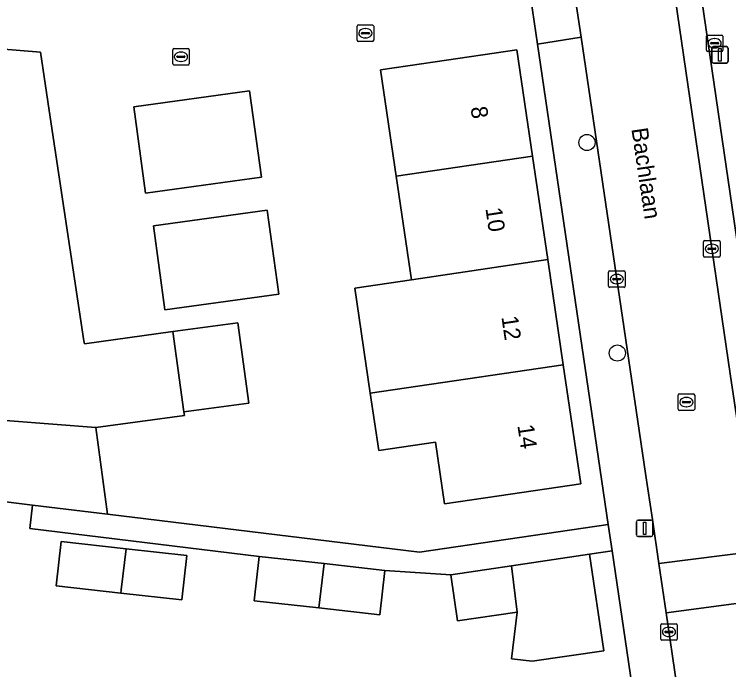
# Model space of a CAD drawing. Extents: x 159053 to 160042, y 380449 to 381423.
# Drawn here: x 159448.97 to 159492.17, y 381206.15 to 381245.81 of the extents above; entities that cross this region are included whole.
import ezdxf

# ---------------------------------------------------------------- set-up
doc = ezdxf.new("R2010")
doc.units = 0
for name, color, linetype in [('IMGEO_Boom', 7, 'Continuous'), ('IMGEO_Brandkraan', 7, 'Continuous'), ('IMGEO_Erf', 7, 'Continuous'), ('IMGEO_Kolk', 7, 'Continuous'), ('IMGEO_Lichtmast', 7, 'Continuous'), ('IMGEO_Openbare_ruimte_label', 7, 'Continuous'), ('IMGEO_Pand', 7, 'Continuous'), ('IMGEO_Pand_nummerreeks', 7, 'Continuous'), ('IMGEO_Parkeervlak_open', 7, 'Continuous'), ('IMGEO_Rijbaan_lokaal_open', 7, 'Continuous'), ('IMGEO_Rioolput', 7, 'Continuous'), ('IMGEO_Voetpad_open', 7, 'Continuous')]:
    doc.layers.add(name, color=color, linetype=linetype)

msp = doc.modelspace()

# ---------------------------------------------------------------- linework, layer by layer
at = {"layer": 'IMGEO_Boom'}
for centre in [(159483.6, 381238.048), (159485.436, 381225.309)]:
    msp.add_circle(centre, 0.489, dxfattribs=at)
at = {"layer": 'IMGEO_Brandkraan'}
for p, q in [((159490.822, 381243.628), (159490.822, 381244.48)), ((159490.897, 381244.554), (159491.749, 381244.554)), ((159491.823, 381244.48), (159491.823, 381243.628)), ((159491.081, 381244.048), (159491.081, 381244.06)), ((159491.519, 381244.011), (159491.121, 381244.011)), ((159491.124, 381244.097), (159491.522, 381244.097)), ((159491.31, 381244.334), (159491.335, 381244.334)), ((159491.565, 381244.06), (159491.565, 381244.048)), ((159491.749, 381243.554), (159490.897, 381243.554)), ((159491.333, 381243.774), (159491.308, 381243.774))]:
    msp.add_line(p, q, dxfattribs=at)
for points in [[(159490.822, 381243.628), (159490.822, 381244.48)], [(159490.897, 381244.554), (159491.749, 381244.554)], [(159491.823, 381244.48), (159491.823, 381243.628)], [(159491.749, 381243.554), (159490.897, 381243.554)]]:
    msp.add_lwpolyline(points, dxfattribs=at)
for centre, radius, start, end in [((159490.899, 381244.478), 0.0765, 91.552, 178.448), ((159490.899, 381244.478), 0.0765, 91.552, 178.448), ((159491.747, 381244.478), 0.0765, 1.552, 88.448), ((159491.747, 381244.478), 0.0765, 1.552, 88.448), ((159491.121, 381244.057), 0.0403, 85.8775, 175.7526), ((159491.118, 381244.047), 0.0366, 178.938, 274.7102), ((159491.522, 381244.054), 0.043, 264.8664, 352.4533), ((159491.526, 381244.059), 0.0386, 1.7309, 96.639), ((159490.899, 381243.63), 0.0765, 181.552, 268.448), ((159490.899, 381243.63), 0.0765, 181.552, 268.448), ((159491.747, 381243.63), 0.0765, 271.552, 358.448), ((159491.747, 381243.63), 0.0765, 271.552, 358.448)]:
    msp.add_arc(centre, radius, start, end, dxfattribs=at)
for centre, major_axis, ratio, start_param, end_param in [((159491.309, 381244.054), (-0.387, 0.002), 0.722429, 4.712389, 7.853982), ((159491.334, 381244.054), (-0.39, 0.002), 0.717154, 1.570796, 4.712389)]:
    msp.add_ellipse(centre, major_axis=major_axis, ratio=ratio, start_param=start_param, end_param=end_param, dxfattribs=at)
at = {"layer": 'IMGEO_Erf'}
for points in [[(159442.411, 381244.175), (159450.548, 381243.517), (159451.14, 381239.591), (159453.182, 381226.043), (159453.205, 381225.876), (159458.563, 381226.605), (159462.483, 381227.139), (159463.144, 381222.283), (159459.224, 381221.75), (159459.254, 381221.532), (159453.896, 381220.798), (159454.61, 381215.559), (159473.478, 381213.258), (159484.891, 381214.936), (159480.617, 381244.005), (159479.909, 381248.818)], [(159488.937, 381187.416), (159485.126, 381213.338), (159483.757, 381213.137), (159484.616, 381207.298), (159480.282, 381206.66), (159479.028, 381206.806), (159479.388, 381209.64), (159475.769, 381209.107), (159475.358, 381211.9), (159471.378, 381212.157), (159471.078, 381209.475), (159467.392, 381209.888), (159463.482, 381210.326), (159463.782, 381213.007), (159449.9, 381214.7), (159450.073, 381216.112), (159443.885, 381216.867)]]:
    msp.add_lwpolyline(points, dxfattribs=at)
for points in [[(159479.36, 381243.661), (159480.307, 381237.228), (159481.23, 381230.965), (159482.166, 381224.604), (159483.228, 381217.393), (159478.282, 381216.665), (159474.983, 381216.179), (159474.432, 381219.923), (159471.004, 381219.421), (159470.494, 381222.883), (159469.558, 381229.242), (159472.985, 381229.748), (159472.063, 381236.011), (159471.115, 381242.447), (159474.414, 381242.933)], [(159463.199, 381241.178), (159463.92, 381235.956), (159456.91, 381234.989), (159456.189, 381240.211)], [(159464.269, 381233.949), (159464.961, 381228.868), (159458.069, 381227.93), (159457.377, 381233.011)], [(159455.415, 381210.79), (159451.506, 381211.228), (159451.806, 381213.909), (159455.734, 381213.469), (159459.402, 381213.059), (159459.102, 381210.377)]]:
    msp.add_lwpolyline(points, close=True, dxfattribs=at)
at = {"layer": 'IMGEO_Kolk'}
for p, q in [((159469.701, 381244.235), (159469.701, 381245.087)), ((159469.776, 381245.161), (159470.628, 381245.161)), ((159470.189, 381244.941), (159470.214, 381244.941)), ((159470.702, 381245.087), (159470.702, 381244.235)), ((159469.96, 381244.655), (159469.96, 381244.667)), ((159470.398, 381244.618), (159470, 381244.618)), ((159470.003, 381244.704), (159470.401, 381244.704)), ((159470.212, 381244.381), (159470.187, 381244.381)), ((159470.444, 381244.667), (159470.444, 381244.655)), ((159470.628, 381244.161), (159469.776, 381244.161)), ((159458.545, 381242.813), (159458.545, 381243.665)), ((159458.62, 381243.739), (159459.472, 381243.739)), ((159459.033, 381243.519), (159459.058, 381243.519)), ((159459.546, 381243.665), (159459.546, 381242.813)), ((159458.804, 381243.233), (159458.804, 381243.245)), ((159459.242, 381243.196), (159458.844, 381243.196)), ((159458.847, 381243.282), (159459.245, 381243.282)), ((159459.288, 381243.245), (159459.288, 381243.233)), ((159459.472, 381242.739), (159458.62, 381242.739)), ((159459.056, 381242.959), (159459.031, 381242.959)), ((159490.655, 381231.192), (159490.655, 381232.044)), ((159490.73, 381232.118), (159491.582, 381232.118)), ((159491.143, 381231.898), (159491.168, 381231.898)), ((159491.656, 381232.044), (159491.656, 381231.192)), ((159490.914, 381231.612), (159490.914, 381231.624)), ((159491.352, 381231.575), (159490.954, 381231.575)), ((159490.957, 381231.661), (159491.355, 381231.661)), ((159491.398, 381231.624), (159491.398, 381231.612)), ((159491.582, 381231.118), (159490.73, 381231.118)), ((159491.166, 381231.338), (159491.141, 381231.338)), ((159484.903, 381229.361), (159484.903, 381230.213)), ((159484.978, 381230.287), (159485.83, 381230.287)), ((159485.904, 381230.213), (159485.904, 381229.361)), ((159485.162, 381229.781), (159485.162, 381229.793)), ((159485.6, 381229.744), (159485.202, 381229.744)), ((159485.205, 381229.83), (159485.603, 381229.83)), ((159485.391, 381230.067), (159485.416, 381230.067)), ((159485.646, 381229.793), (159485.646, 381229.781)), ((159485.83, 381229.287), (159484.978, 381229.287)), ((159485.414, 381229.507), (159485.389, 381229.507)), ((159488.134, 381208.934), (159488.986, 381208.934)), ((159488.059, 381208.008), (159488.059, 381208.86)), ((159488.547, 381208.714), (159488.572, 381208.714)), ((159489.06, 381208.86), (159489.06, 381208.008)), ((159488.318, 381208.428), (159488.318, 381208.44)), ((159488.756, 381208.391), (159488.358, 381208.391)), ((159488.361, 381208.477), (159488.759, 381208.477)), ((159488.57, 381208.154), (159488.545, 381208.154)), ((159488.802, 381208.44), (159488.802, 381208.428)), ((159488.986, 381207.934), (159488.134, 381207.934))]:
    msp.add_line(p, q, dxfattribs=at)
for points in [[(159469.701, 381244.235), (159469.701, 381245.087)], [(159469.776, 381245.161), (159470.628, 381245.161)], [(159470.702, 381245.087), (159470.702, 381244.235)], [(159470.628, 381244.161), (159469.776, 381244.161)], [(159458.545, 381242.813), (159458.545, 381243.665)], [(159458.62, 381243.739), (159459.472, 381243.739)], [(159459.546, 381243.665), (159459.546, 381242.813)], [(159459.472, 381242.739), (159458.62, 381242.739)], [(159490.655, 381231.192), (159490.655, 381232.044)], [(159490.73, 381232.118), (159491.582, 381232.118)], [(159491.656, 381232.044), (159491.656, 381231.192)], [(159491.582, 381231.118), (159490.73, 381231.118)], [(159484.903, 381229.361), (159484.903, 381230.213)], [(159484.978, 381230.287), (159485.83, 381230.287)], [(159485.904, 381230.213), (159485.904, 381229.361)], [(159485.83, 381229.287), (159484.978, 381229.287)], [(159488.134, 381208.934), (159488.986, 381208.934)], [(159488.059, 381208.008), (159488.059, 381208.86)], [(159489.06, 381208.86), (159489.06, 381208.008)], [(159488.986, 381207.934), (159488.134, 381207.934)]]:
    msp.add_lwpolyline(points, dxfattribs=at)
for centre, radius, start, end in [((159469.778, 381245.085), 0.0765, 91.552, 178.448), ((159469.778, 381245.085), 0.0765, 91.552, 178.448), ((159470.626, 381245.085), 0.0765, 1.552, 88.448), ((159470.626, 381245.085), 0.0765, 1.552, 88.448), ((159470, 381244.664), 0.0403, 85.8775, 175.7526), ((159469.997, 381244.654), 0.0366, 178.938, 274.7102), ((159470.401, 381244.661), 0.043, 264.8664, 352.4533), ((159470.405, 381244.666), 0.0386, 1.7309, 96.639), ((159469.778, 381244.237), 0.0765, 181.552, 268.448), ((159469.778, 381244.237), 0.0765, 181.552, 268.448), ((159470.626, 381244.237), 0.0765, 271.552, 358.448), ((159470.626, 381244.237), 0.0765, 271.552, 358.448), ((159458.622, 381243.663), 0.0765, 91.552, 178.448), ((159458.622, 381243.663), 0.0765, 91.552, 178.448), ((159459.47, 381243.663), 0.0765, 1.552, 88.448), ((159459.47, 381243.663), 0.0765, 1.552, 88.448), ((159458.844, 381243.242), 0.0403, 85.8775, 175.7526), ((159458.841, 381243.232), 0.0366, 178.938, 274.7102), ((159459.245, 381243.239), 0.043, 264.8664, 352.4533), ((159459.249, 381243.244), 0.0386, 1.7309, 96.639), ((159458.622, 381242.815), 0.0765, 181.552, 268.448), ((159458.622, 381242.815), 0.0765, 181.552, 268.448), ((159459.47, 381242.815), 0.0765, 271.552, 358.448), ((159459.47, 381242.815), 0.0765, 271.552, 358.448), ((159490.732, 381232.042), 0.0765, 91.552, 178.448), ((159490.732, 381232.042), 0.0765, 91.552, 178.448), ((159491.58, 381232.042), 0.0765, 1.552, 88.448), ((159491.58, 381232.042), 0.0765, 1.552, 88.448), ((159490.954, 381231.621), 0.0403, 85.8775, 175.7526), ((159490.951, 381231.611), 0.0366, 178.938, 274.7102), ((159491.355, 381231.618), 0.043, 264.8664, 352.4533), ((159491.359, 381231.623), 0.0386, 1.7309, 96.639), ((159490.732, 381231.194), 0.0765, 181.552, 268.448), ((159490.732, 381231.194), 0.0765, 181.552, 268.448), ((159491.58, 381231.194), 0.0765, 271.552, 358.448), ((159491.58, 381231.194), 0.0765, 271.552, 358.448), ((159484.98, 381230.211), 0.0765, 91.552, 178.448), ((159484.98, 381230.211), 0.0765, 91.552, 178.448), ((159485.828, 381230.211), 0.0765, 1.552, 88.448), ((159485.828, 381230.211), 0.0765, 1.552, 88.448), ((159485.202, 381229.79), 0.0403, 85.8775, 175.7526), ((159485.199, 381229.78), 0.0366, 178.938, 274.7102), ((159485.603, 381229.787), 0.043, 264.8664, 352.4533), ((159485.607, 381229.792), 0.0386, 1.7309, 96.639), ((159484.98, 381229.363), 0.0765, 181.552, 268.448), ((159484.98, 381229.363), 0.0765, 181.552, 268.448), ((159485.828, 381229.363), 0.0765, 271.552, 358.448), ((159485.828, 381229.363), 0.0765, 271.552, 358.448), ((159488.136, 381208.858), 0.0765, 91.552, 178.448), ((159488.136, 381208.858), 0.0765, 91.552, 178.448), ((159488.984, 381208.858), 0.0765, 1.552, 88.448), ((159488.984, 381208.858), 0.0765, 1.552, 88.448), ((159488.358, 381208.437), 0.0403, 85.8775, 175.7526), ((159488.355, 381208.427), 0.0366, 178.938, 274.7102), ((159488.759, 381208.434), 0.043, 264.8664, 352.4533), ((159488.763, 381208.439), 0.0386, 1.7309, 96.639), ((159488.136, 381208.01), 0.0765, 181.552, 268.448), ((159488.136, 381208.01), 0.0765, 181.552, 268.448), ((159488.984, 381208.01), 0.0765, 271.552, 358.448), ((159488.984, 381208.01), 0.0765, 271.552, 358.448)]:
    msp.add_arc(centre, radius, start, end, dxfattribs=at)
for centre, major_axis, ratio, start_param, end_param in [((159470.188, 381244.661), (-0.387, 0.002), 0.722429, 4.712389, 7.853982), ((159470.213, 381244.661), (-0.39, 0.002), 0.717154, 1.570796, 4.712389), ((159459.032, 381243.239), (-0.387, 0.002), 0.722429, 4.712389, 7.853982), ((159459.057, 381243.239), (-0.39, 0.002), 0.717154, 1.570796, 4.712389), ((159491.142, 381231.618), (-0.387, 0.002), 0.722429, 4.712389, 7.853982), ((159491.167, 381231.618), (-0.39, 0.002), 0.717154, 1.570796, 4.712389), ((159485.39, 381229.787), (-0.387, 0.002), 0.722429, 4.712389, 7.853982), ((159485.415, 381229.787), (-0.39, 0.002), 0.717154, 1.570796, 4.712389), ((159488.546, 381208.434), (-0.387, 0.002), 0.722429, 4.712389, 7.853982), ((159488.571, 381208.434), (-0.39, 0.002), 0.717154, 1.570796, 4.712389)]:
    msp.add_ellipse(centre, major_axis=major_axis, ratio=ratio, start_param=start_param, end_param=end_param, dxfattribs=at)
at = {"layer": 'IMGEO_Lichtmast'}
for p, q in [((159491.144, 381242.955), (159491.144, 381243.755)), ((159491.144, 381243.755), (159491.144, 381242.955)), ((159491.244, 381243.855), (159492.034, 381243.855)), ((159492.034, 381243.855), (159491.244, 381243.855)), ((159492.134, 381243.755), (159492.134, 381242.955)), ((159492.134, 381242.955), (159492.134, 381243.755)), ((159492.034, 381242.855), (159491.244, 381242.855)), ((159491.244, 381242.855), (159492.034, 381242.855)), ((159486.591, 381214.303), (159486.591, 381215.103)), ((159486.591, 381215.103), (159486.591, 381214.303)), ((159486.691, 381215.203), (159487.481, 381215.203)), ((159487.481, 381215.203), (159486.691, 381215.203)), ((159487.581, 381215.103), (159487.581, 381214.303)), ((159487.581, 381214.303), (159487.581, 381215.103)), ((159487.481, 381214.203), (159486.691, 381214.203)), ((159486.691, 381214.203), (159487.481, 381214.203))]:
    msp.add_line(p, q, dxfattribs=at)
for points in [[(159491.564, 381243.73), (159491.714, 381243.73), (159491.714, 381242.98), (159491.564, 381242.98), (159491.564, 381243.73)], [(159487.011, 381215.078), (159487.161, 381215.078), (159487.161, 381214.328), (159487.011, 381214.328), (159487.011, 381215.078)]]:
    msp.add_lwpolyline(points, dxfattribs=at)
for centre, start, end in [((159491.244, 381243.755), 90, 180), ((159491.244, 381243.755), 90, 180), ((159492.034, 381243.755), 0, 90), ((159492.034, 381243.755), 360, 90), ((159491.244, 381242.955), 180, 270), ((159491.244, 381242.955), 180, 270), ((159492.034, 381242.955), 270, 0), ((159492.034, 381242.955), 270, 0), ((159486.691, 381215.103), 90, 180), ((159486.691, 381215.103), 90, 180), ((159487.481, 381215.103), 0, 90), ((159487.481, 381215.103), 360, 90), ((159486.691, 381214.303), 180, 270), ((159486.691, 381214.303), 180, 270), ((159487.481, 381214.303), 270, 0), ((159487.481, 381214.303), 270, 0)]:
    msp.add_arc(centre, 0.1, start, end, dxfattribs=at)
at = {"layer": 'IMGEO_Pand'}
for points in [[(159451.14, 381239.591), (159450.548, 381243.517), (159442.411, 381244.175), (159442.222, 381242.059), (159441.156, 381226.061), (159440.873, 381221.815), (159453.896, 381220.798), (159459.254, 381221.532), (159459.224, 381221.75), (159458.563, 381226.605), (159453.205, 381225.876), (159453.182, 381226.043)], [(159480.307, 381237.228), (159479.36, 381243.661), (159474.414, 381242.933), (159471.115, 381242.447), (159472.063, 381236.011)], [(159463.199, 381241.178), (159456.189, 381240.211), (159456.91, 381234.989), (159463.92, 381235.956)], [(159480.307, 381237.228), (159472.063, 381236.011), (159472.985, 381229.748), (159481.23, 381230.965)], [(159457.377, 381233.011), (159458.069, 381227.93), (159464.961, 381228.868), (159464.269, 381233.949)], [(159470.494, 381222.883), (159482.166, 381224.604), (159481.23, 381230.965), (159472.985, 381229.748), (159469.558, 381229.242)], [(159458.563, 381226.605), (159459.224, 381221.75), (159463.144, 381222.283), (159462.483, 381227.139)], [(159470.494, 381222.883), (159471.004, 381219.421), (159474.432, 381219.923), (159474.983, 381216.179), (159478.282, 381216.665), (159483.228, 381217.393), (159482.166, 381224.604)], [(159453.896, 381220.798), (159440.873, 381221.815), (159440.57, 381217.271), (159443.885, 381216.867), (159450.073, 381216.112), (159454.61, 381215.559)], [(159455.734, 381213.469), (159451.806, 381213.909), (159451.506, 381211.228), (159455.415, 381210.79), (159455.438, 381210.981)], [(159455.734, 381213.469), (159455.438, 381210.981), (159455.415, 381210.79), (159459.102, 381210.377), (159459.402, 381213.059)], [(159467.392, 381209.888), (159467.711, 381212.567), (159463.782, 381213.007), (159463.482, 381210.326)], [(159479.388, 381209.64), (159479.028, 381206.806), (159480.282, 381206.66), (159484.616, 381207.298), (159483.757, 381213.137), (159479.036, 381212.442)], [(159467.392, 381209.888), (159471.078, 381209.475), (159471.378, 381212.157), (159467.711, 381212.567)], [(159479.388, 381209.64), (159479.036, 381212.442), (159475.358, 381211.9), (159475.769, 381209.107)]]:
    msp.add_lwpolyline(points, close=True, dxfattribs=at)
at = {"layer": 'IMGEO_Parkeervlak_open'}
for points in [[(159486.361, 381264.417), (159486.669, 381262.342), (159486.847, 381261.146), (159488.473, 381250), (159492.258, 381224.048), (159493.062, 381218.662)], [(159494.208, 381221.574), (159490.06, 381250), (159488.271, 381262.261)]]:
    msp.add_lwpolyline(points, dxfattribs=at)
at = {"layer": 'IMGEO_Rijbaan_lokaal_open'}
for points in [[(159488.473, 381250), (159486.847, 381261.146), (159486.669, 381262.342), (159480.703, 381261.448), (159482.417, 381250), (159482.532, 381249.232), (159483.241, 381244.433), (159487.143, 381218.031), (159487.557, 381215.23), (159487.948, 381212.582), (159493.859, 381213.326), (159493.18, 381217.872), (159493.062, 381218.662), (159492.258, 381224.048)], [(159454.61, 381215.559), (159450.073, 381216.112), (159449.9, 381214.7), (159463.782, 381213.007), (159467.711, 381212.567), (159471.378, 381212.157), (159475.358, 381211.9), (159479.036, 381212.442), (159483.757, 381213.137), (159485.126, 381213.338), (159484.891, 381214.936), (159473.478, 381213.258)], [(159493.983, 381212.494), (159493.859, 381213.326), (159487.948, 381212.582), (159488.389, 381209.601), (159494.299, 381210.378)], [(159495.865, 381199.882), (159494.908, 381206.294), (159494.366, 381209.923), (159494.299, 381210.378), (159488.389, 381209.601), (159489.023, 381205.31), (159489.612, 381201.327), (159489.808, 381199.999), (159491.467, 381188.558), (159497.399, 381189.453), (159496.908, 381192.969)]]:
    msp.add_lwpolyline(points, close=True, dxfattribs=at)
at = {"layer": 'IMGEO_Rioolput'}
for p, q in [((159489.114, 381221.917), (159489.114, 381222.769)), ((159489.189, 381222.843), (159490.041, 381222.843)), ((159490.115, 381222.769), (159490.115, 381221.917)), ((159489.373, 381222.337), (159489.373, 381222.349)), ((159489.416, 381222.386), (159489.814, 381222.386)), ((159489.602, 381222.623), (159489.627, 381222.623)), ((159489.857, 381222.349), (159489.857, 381222.337)), ((159489.811, 381222.3), (159489.413, 381222.3)), ((159489.625, 381222.063), (159489.6, 381222.063)), ((159490.041, 381221.843), (159489.189, 381221.843))]:
    msp.add_line(p, q, dxfattribs=at)
for points in [[(159489.114, 381221.917), (159489.114, 381222.769)], [(159489.189, 381222.843), (159490.041, 381222.843)], [(159490.115, 381222.769), (159490.115, 381221.917)], [(159490.041, 381221.843), (159489.189, 381221.843)]]:
    msp.add_lwpolyline(points, dxfattribs=at)
for centre, radius, start, end in [((159489.191, 381222.767), 0.0765, 91.552, 178.448), ((159489.191, 381222.767), 0.0765, 91.552, 178.448), ((159490.039, 381222.767), 0.0765, 1.552, 88.448), ((159490.039, 381222.767), 0.0765, 1.552, 88.448), ((159489.413, 381222.346), 0.0403, 85.8775, 175.7526), ((159489.41, 381222.336), 0.0366, 178.938, 274.7102), ((159489.814, 381222.343), 0.043, 264.8664, 352.4533), ((159489.818, 381222.348), 0.0386, 1.7309, 96.639), ((159489.191, 381221.919), 0.0765, 181.552, 268.448), ((159489.191, 381221.919), 0.0765, 181.552, 268.448), ((159490.039, 381221.919), 0.0765, 271.552, 358.448), ((159490.039, 381221.919), 0.0765, 271.552, 358.448)]:
    msp.add_arc(centre, radius, start, end, dxfattribs=at)
for centre, major_axis, ratio, start_param, end_param in [((159489.601, 381222.343), (-0.387, 0.002), 0.722429, 4.712389, 7.853982), ((159489.626, 381222.343), (-0.39, 0.002), 0.717154, 1.570796, 4.712389)]:
    msp.add_ellipse(centre, major_axis=major_axis, ratio=ratio, start_param=start_param, end_param=end_param, dxfattribs=at)
at = {"layer": 'IMGEO_Voetpad_open'}
for points in [[(159488.271, 381262.261), (159490.06, 381250), (159494.208, 381221.574)], [(159487.557, 381215.23), (159487.143, 381218.031), (159483.241, 381244.433), (159480.617, 381244.005), (159484.891, 381214.936), (159485.126, 381213.338), (159488.937, 381187.416), (159489.16, 381185.654), (159491.782, 381185.731)], [(159491.725, 381186.819), (159491.467, 381188.558), (159489.808, 381199.999), (159489.612, 381201.327), (159489.023, 381205.31), (159488.389, 381209.601), (159487.948, 381212.582), (159487.557, 381215.23)]]:
    msp.add_lwpolyline(points, dxfattribs=at)
msp.add_lwpolyline([(159482.532, 381249.232), (159479.909, 381248.818), (159480.617, 381244.005), (159483.241, 381244.433)], close=True, dxfattribs=at)

# ---------------------------------------------------------------- texts
at = {"layer": 'IMGEO_Openbare_ruimte_label'}
msp.add_text('Bachlaan', height=1, rotation=278.3976, dxfattribs=at).set_placement((159486.284, 381238.877))
at = {"layer": 'IMGEO_Pand_nummerreeks'}
for s, p in [('8', (159476.558, 381240.168)), ('10', (159477.458, 381234.057)), ('12', (159478.424, 381227.496)), ('14', (159479.392, 381220.926))]:
    msp.add_text(s, height=1, rotation=278.3767, dxfattribs=at).set_placement(p)

doc.saveas('drawing.dxf')
